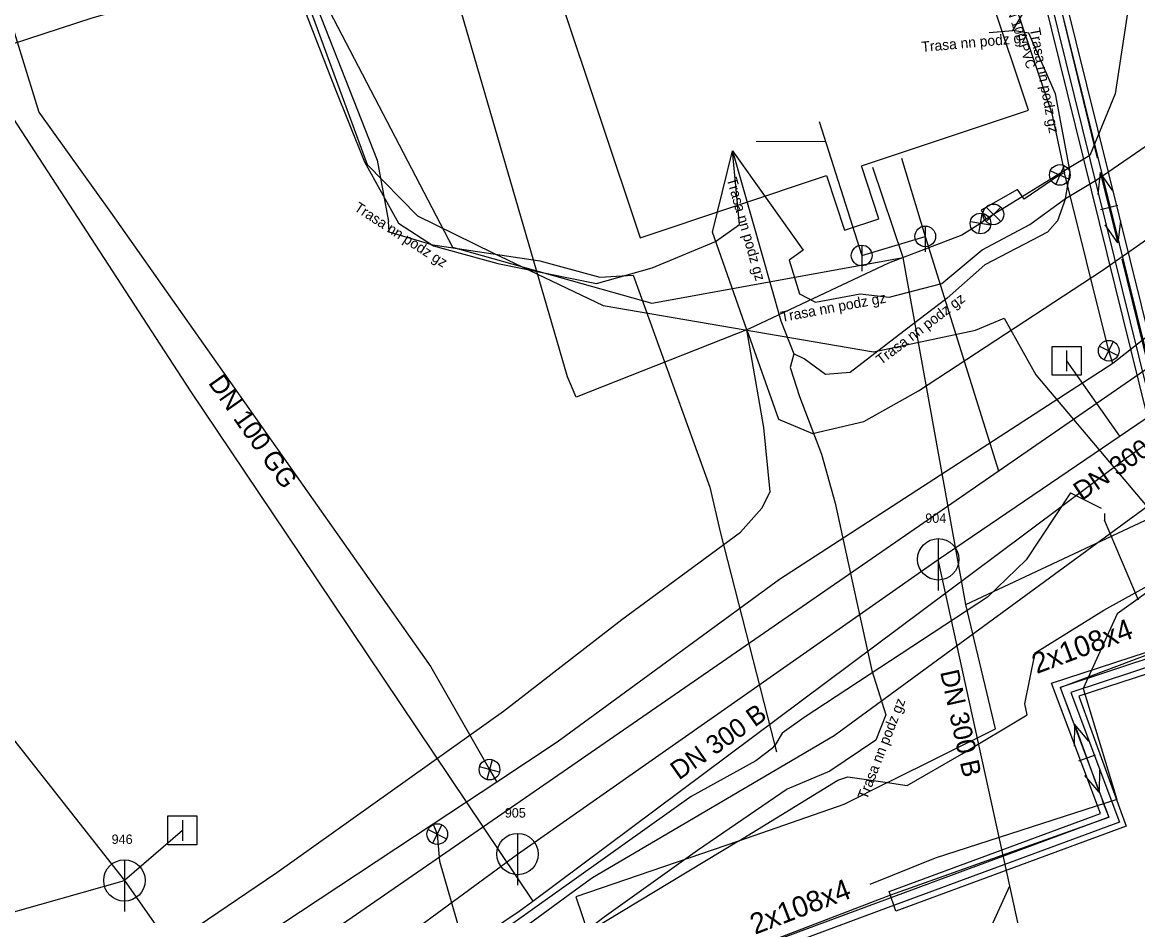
# Model space of a CAD drawing. Extents: x -492431 to -49223, y -1127123 to -112687.
# Drawn here: x -492298.3 to -492244.4, y -1127017.5 to -1126974.3 of the extents above; entities that cross this region are included whole.
import ezdxf

# ---------------------------------------------------------------- set-up
doc = ezdxf.new("R2010")
doc.units = 0
for name, color, linetype in [('Vrstva 1', 7, 'Continuous'), ('Vrstva 11', 7, 'Continuous'), ('Vrstva 15', 7, 'Continuous'), ('Vrstva 17', 7, 'Continuous'), ('Vrstva 19', 7, 'Continuous'), ('Vrstva 20', 7, 'Continuous'), ('Vrstva 22', 7, 'Continuous'), ('Vrstva 24', 7, 'Continuous'), ('Vrstva 26', 7, 'Continuous'), ('Vrstva 35', 7, 'Continuous'), ('Vrstva 44', 7, 'Continuous'), ('Vrstva 45', 7, 'Continuous'), ('Vrstva 49', 7, 'Continuous'), ('Vrstva 5', 7, 'Continuous'), ('Vrstva 6', 7, 'Continuous'), ('Vrstva 9', 7, 'Continuous')]:
    doc.layers.add(name, color=color, linetype=linetype)

msp = doc.modelspace()

# ---------------------------------------------------------------- linework, layer by layer
at = {"layer": 'Vrstva 1'}
for points in [[(-492325.249, -1126898.739), (-492322.642, -1126907.396), (-492319.91, -1126916.162), (-492316.366, -1126927.531), (-492313.526, -1126937.493), (-492311.824, -1126943.46), (-492307.449, -1126957.644), (-492305.431, -1126964.56), (-492304.672, -1126966.837), (-492303.375, -1126970.726), (-492302.901, -1126972.466), (-492290.152, -1126992.096), (-492284.841, -1127000), (-492275.169, -1127014.395), (-492273.59, -1127016.746)], [(-492311.084, -1127042.338), (-492308.422, -1127040.519), (-492280.878, -1127021.698), (-492274.246, -1127017.236), (-492273.59, -1127016.746), (-492251.166, -1127000), (-492244.915, -1126995.332), (-492241.648, -1126993.025), (-492237.012, -1126989.75)]]:
    msp.add_lwpolyline(points, dxfattribs=at)
at = {"layer": 'Vrstva 11'}
for points in [[(-492295.29, -1126949.58), (-492293.18, -1126956.81), (-492288.33, -1126969.66), (-492285.99, -1126968.78), (-492277.47, -1126985.14), (-492267.85, -1126987.85), (-492255.7, -1126985.65)], [(-492212.36, -1126974.41), (-492232.81, -1126989.56), (-492259.04, -1127008.76), (-492270.71, -1127015.63)], [(-492255.7, -1126985.65), (-492257.16, -1126981.29)], [(-492252.68, -1127002.42), (-492255.7, -1126985.65)], [(-492252.68, -1127002.42), (-492240.08, -1126996.5), (-492239.44, -1126998.4)], [(-492256.45, -1127011.02), (-492255.5, -1127011.16), (-492252.88, -1127009.65), (-492249.71, -1127007.75), (-492249.83, -1127007.22), (-492249.33, -1127004.75), (-492246, -1127002.69), (-492242.83, -1127000.94), (-492239.33, -1126998.73)], [(-492256.45, -1127011.02), (-492251.24, -1127008.42), (-492252.68, -1127002.42)], [(-492263.66, -1127013.85), (-492258.85, -1127010.91), (-492258.38, -1127010.75), (-492256.45, -1127011.02)], [(-492256.45, -1127011.02), (-492258.57, -1127012.08), (-492263.66, -1127013.85)], [(-492263.66, -1127013.85), (-492271.51, -1127016.54), (-492270.94, -1127018.25)], [(-492263.66, -1127013.85), (-492270.94, -1127018.25)], [(-492270.71, -1127015.63), (-492271.65, -1127016.3), (-492296.86, -1127034.79), (-492304.07, -1127039.47)]]:
    msp.add_lwpolyline(points, dxfattribs=at)
at = {"layer": 'Vrstva 15'}
for p, q in [((-492259.759, -1126979.073), (-492257.706, -1126985.55)), ((-492262.811, -1126980.031), (-492259.454, -1126980.036)), ((-492255.781, -1126980.848), (-492254.634, -1126984.625)), ((-492319.259, -1126982.82), (-492293.327, -1127015.749)), ((-492257.706, -1126985.55), (-492254.634, -1126984.625)), ((-492254.634, -1126984.625), (-492251.095, -1126995.958)), ((-492254.006, -1127000.233), (-492235.336, -1126987.536)), ((-492247.807, -1126990.639), (-492245.254, -1126994.28)), ((-492274.331, -1127014.474), (-492254.006, -1127000.233)), ((-492250.545, -1127016.013), (-492254.006, -1127000.233)), ((-492290.527, -1127013.33), (-492293.327, -1127015.749)), ((-492287.427, -1127024.093), (-492274.331, -1127014.474)), ((-492307.936, -1127019.882), (-492293.327, -1127015.749)), ((-492293.327, -1127015.749), (-492287.427, -1127024.093)), ((-492252.489, -1127020.253), (-492250.544, -1127016.013)), ((-492247.397, -1127030.362), (-492250.545, -1127016.013))]:
    msp.add_line(p, q, dxfattribs=at)
msp.add_lwpolyline([(-492348.18, -1127063.194), (-492288.462, -1127021.762), (-492226.623, -1126979.059)], dxfattribs=at)
at = {"layer": 'Vrstva 17'}
for p, q in [((-492254.634, -1126984.125), (-492254.634, -1126985.375)), ((-492257.706, -1126985.05), (-492257.706, -1126986.3)), ((-492247.807, -1126990.139), (-492247.807, -1126991.139)), ((-492254.006, -1126999.233), (-492254.006, -1127001.733)), ((-492290.527, -1127012.83), (-492290.527, -1127013.83)), ((-492274.331, -1127013.474), (-492274.331, -1127015.974)), ((-492293.327, -1127014.749), (-492293.327, -1127017.249))]:
    msp.add_line(p, q, dxfattribs=at)
for points in [[(-492248.507, -1126989.939), (-492247.108, -1126989.939), (-492247.108, -1126991.339), (-492248.507, -1126991.339), (-492248.507, -1126989.939)], [(-492291.227, -1127012.631), (-492289.828, -1127012.631), (-492289.828, -1127014.03), (-492291.227, -1127014.03), (-492291.227, -1127012.631)]]:
    msp.add_lwpolyline(points, dxfattribs=at)
for centre, radius in [((-492254.634, -1126984.625), 0.5), ((-492257.706, -1126985.55), 0.5), ((-492254.006, -1127000.233), 1), ((-492274.331, -1127014.474), 1), ((-492293.327, -1127015.749), 1)]:
    msp.add_circle(centre, radius, dxfattribs=at)
at = {"layer": 'Vrstva 20'}
for p, q in [((-492302.176, -1126963.33), (-492297.462, -1126978.624)), ((-492297.462, -1126978.624), (-492294.001, -1126983.458)), ((-492247.905, -1126981.562), (-492248.131, -1126981.658)), ((-492245.77, -1126990.15), (-492247.905, -1126981.562)), ((-492294.001, -1126983.458), (-492278.528, -1127005.422)), ((-492251.683, -1126983.801), (-492251.966, -1126984.002)), ((-492245.569, -1126990.776), (-492245.77, -1126990.15)), ((-492278.528, -1127005.422), (-492275.687, -1127010.392)), ((-492275.687, -1127010.392), (-492275.341, -1127011)), ((-492275.341, -1127011), (-492278.406, -1127013.025)), ((-492278.406, -1127013.025), (-492278.21, -1127013.51))]:
    msp.add_line(p, q, dxfattribs=at)
for points in [[(-492258.655, -1126937.855), (-492256.335, -1126940.299), (-492254.087, -1126946.247), (-492250.053, -1126957.353), (-492247.459, -1126963.781), (-492245.575, -1126969.401), (-492244.821, -1126973.507), (-492245.464, -1126977.737), (-492246.677, -1126980.722), (-492247.678, -1126981.308), (-492251.339, -1126983.561)], [(-492251.966, -1126984.002), (-492252.867, -1126984.562), (-492256.417, -1126985.913), (-492263.134, -1126989.093), (-492271.494, -1126992.401), (-492271.919, -1126991.405), (-492277.913, -1126970.81), (-492278.388, -1126969.283), (-492287.981, -1126972.121), (-492294.895, -1126974.083), (-492300.39, -1126975.871), (-492310.81, -1126979.945), (-492316.118, -1126984.31), (-492323.327, -1126989.676), (-492325.365, -1126991.119)], [(-492252.187, -1126972.839), (-492250.649, -1126972.391), (-492248.52, -1126978.691), (-492248.003, -1126981.105), (-492247.905, -1126981.562)], [(-492248.131, -1126981.658), (-492249.857, -1126982.82), (-492250.172, -1126982.359), (-492251.938, -1126983.356), (-492251.683, -1126983.801)], [(-492251.339, -1126983.561), (-492251.393, -1126983.594), (-492251.683, -1126983.801)], [(-492225.92, -1127031.19), (-492226.098, -1127030.529), (-492230.807, -1127017.938), (-492238.16, -1126995.84), (-492239.164, -1126992.202), (-492241.237, -1126987.362), (-492245.569, -1126990.776)], [(-492245.569, -1126990.776), (-492261.681, -1127001.199), (-492272.42, -1127009.071), (-492275.341, -1127011)], [(-492278.406, -1127013.025), (-492299.412, -1127026.894), (-492316.583, -1127039.151), (-492312.88, -1127049.25), (-492307.84, -1127067.71), (-492302.01, -1127083.53), (-492298.428, -1127092.757)], [(-492278.21, -1127013.51), (-492278.11, -1127014.81), (-492277.09, -1127018.33), (-492276.55, -1127020.13), (-492263.48, -1127057.09), (-492263.27, -1127057.7)]]:
    msp.add_lwpolyline(points, dxfattribs=at)
at = {"layer": 'Vrstva 22'}
for p, q in [((-492247.929, -1126981.206), (-492248.333, -1126982.11)), ((-492248.583, -1126981.456), (-492247.679, -1126981.86)), ((-492252.048, -1126984.49), (-492251.884, -1126983.514)), ((-492251.689, -1126983.911), (-492250.989, -1126983.211)), ((-492250.989, -1126983.911), (-492251.689, -1126983.211)), ((-492251.478, -1126984.084), (-492252.454, -1126983.92)), ((-492246.211, -1126989.924), (-492245.329, -1126990.376)), ((-492245.996, -1126990.591), (-492245.544, -1126989.709)), ((-492275.557, -1127009.914), (-492275.817, -1127010.87)), ((-492275.209, -1127010.522), (-492276.165, -1127010.262)), ((-492278.432, -1127013.952), (-492277.988, -1127013.068)), ((-492278.652, -1127013.288), (-492277.768, -1127013.732))]:
    msp.add_line(p, q, dxfattribs=at)
for centre, radius in [((-492248.131, -1126981.658), 0.5), ((-492248.131, -1126981.658), 0.025), ((-492251.339, -1126983.561), 0.5), ((-492251.966, -1126984.002), 0.5), ((-492251.339, -1126983.561), 0.025), ((-492251.966, -1126984.002), 0.025), ((-492245.77, -1126990.15), 0.5), ((-492245.77, -1126990.15), 0.025), ((-492275.687, -1127010.392), 0.5), ((-492275.687, -1127010.392), 0.025), ((-492278.21, -1127013.51), 0.5), ((-492278.21, -1127013.51), 0.025)]:
    msp.add_circle(centre, radius, dxfattribs=at)
at = {"layer": 'Vrstva 26'}
for p, q in [((-492284.85, -1126971.41), (-492281.12, -1126980.95)), ((-492281.12, -1126980.95), (-492280.56, -1126983.9)), ((-492280.54, -1126984.43), (-492280.56, -1126983.9)), ((-492278.52, -1126985.02), (-492280.54, -1126984.43)), ((-492278.52, -1126985.02), (-492273.26, -1126985.81)), ((-492273.26, -1126985.81), (-492270.35, -1126986.59)), ((-492270.35, -1126986.59), (-492268.74, -1126986.5)), ((-492268.74, -1126986.5), (-492265.05, -1126996.75)), ((-492265.05, -1126996.75), (-492264.54, -1126998.91)), ((-492247.62, -1126997.02), (-492249.76, -1127000.26)), ((-492247.62, -1126997.02), (-492246.14, -1126997.76)), ((-492245.97, -1126998.01), (-492245.97, -1126998.34)), ((-492244.33, -1127002.2), (-492245.97, -1126998.34)), ((-492264.54, -1126998.91), (-492261.9, -1127009.22)), ((-492249.76, -1127000.26), (-492251.62, -1127002.06)), ((-492251.62, -1127002.06), (-492260.49, -1127007.88)), ((-492260.49, -1127007.88), (-492261.55, -1127008.63)), ((-492261.55, -1127008.63), (-492261.9, -1127009.22)), ((-492262.01, -1127009.35), (-492262.82, -1127009.97)), ((-492262.01, -1127009.35), (-492261.9, -1127009.22)), ((-492261.9, -1127009.22), (-492261.82, -1127009.54)), ((-492262.82, -1127009.97), (-492265.94, -1127011.7)), ((-492265.94, -1127011.7), (-492274.67, -1127017.91))]:
    msp.add_line(p, q, dxfattribs=at)
at = {"layer": 'Vrstva 35'}
for points in [[(-492294.32, -1126954.25), (-492289.61, -1126968.74), (-492285.36, -1126971.01), (-492284.64, -1126972.86), (-492281.6, -1126981.15), (-492279.17, -1126983.63), (-492275.52, -1126985.42), (-492270.19, -1126987.97), (-492257.13, -1126990.21), (-492252.21, -1126989.15), (-492250.82, -1126988.57), (-492249.29, -1126991.31), (-492241.74, -1127000.27)], [(-492241.74, -1127000.27), (-492245.36, -1127002.86), (-492247.01, -1127006.47), (-492245.37, -1127011.84), (-492254.16, -1127014.67), (-492257.31, -1127015.95)]]:
    msp.add_lwpolyline(points, dxfattribs=at)
at = {"layer": 'Vrstva 44'}
for p, q in [((-492248.69, -1126969.86), (-492240.68, -1127002.2)), ((-492241.65, -1127002.44), (-492249.37, -1126971.21)), ((-492248.54, -1127006.21), (-492241.95, -1127004.07)), ((-492241.7, -1127005.04), (-492247.21, -1127006.85)), ((-492246.16, -1127012.52), (-492248.54, -1127006.21)), ((-492247.21, -1127006.85), (-492244.92, -1127013.13)), ((-492256.37, -1127016.29), (-492246.16, -1127012.52)), ((-492244.92, -1127013.13), (-492256.06, -1127017.24)), ((-492256.06, -1127017.24), (-492256.37, -1127016.29))]:
    msp.add_line(p, q, dxfattribs=at)
at = {"layer": 'Vrstva 45'}
for p, q in [((-492240.57, -1127003.92), (-492248.9, -1126970.26)), ((-492248.88, -1126970.33), (-492246.32, -1126980.84)), ((-492240.97, -1127003.97), (-492249.15, -1126970.82)), ((-492246.178, -1126981.545), (-492245.33, -1126984.94)), ((-492245.336, -1126983.138), (-492246.171, -1126983.347)), ((-492245.58, -1126984.17), (-492245.58, -1126984.17)), ((-492245.13, -1126985.72), (-492240.37, -1127005.23)), ((-492248.12, -1127006.42), (-492238.35, -1127002.76)), ((-492240.95, -1127004.05), (-492248.12, -1127006.42)), ((-492240.69, -1127004.39), (-492247.6, -1127006.67)), ((-492248.12, -1127006.42), (-492247.64, -1127007.69)), ((-492248.12, -1127006.42), (-492245.77, -1127012.69)), ((-492247.6, -1127006.67), (-492245.25, -1127012.93)), ((-492247.419, -1127008.198), (-492246.23, -1127011.49)), ((-492246.42, -1127009.698), (-492247.229, -1127009.99)), ((-492246.08, -1127011.88), (-492245.77, -1127012.69)), ((-492246.04, -1127011.97), (-492246.04, -1127011.97)), ((-492245.77, -1127012.69), (-492256.47, -1127016.65)), ((-492256.3, -1127016.44), (-492245.77, -1127012.69)), ((-492245.25, -1127012.93), (-492256.42, -1127017.05)), ((-492246.55, -1127012.97), (-492246.55, -1127012.97)), ((-492268.47, -1127021.1), (-492256.3, -1127016.44)), ((-492256.47, -1127016.65), (-492267.16, -1127020.6)), ((-492256.42, -1127017.05), (-492266.76, -1127020.88))]:
    msp.add_line(p, q, dxfattribs=at)
for points in [[(-492245.571, -1126982.424), (-492246.178, -1126981.545), (-492246.299, -1126982.606)], [(-492245.208, -1126983.879), (-492245.33, -1126984.94), (-492245.936, -1126984.061)], [(-492246.727, -1127009.012), (-492247.419, -1127008.198), (-492247.432, -1127009.266)], [(-492246.217, -1127010.422), (-492246.23, -1127011.49), (-492246.922, -1127010.677)]]:
    msp.add_lwpolyline(points, dxfattribs=at)
at = {"layer": 'Vrstva 49'}
for p, q in [((-492275.01, -1126964.93), (-492268.41, -1126984.69)), ((-492249.64, -1126978.52), (-492252.31, -1126970.54)), ((-492257.72, -1126981.22), (-492249.64, -1126978.52)), ((-492256.87, -1126983.77), (-492257.72, -1126981.22)), ((-492268.41, -1126984.69), (-492259.41, -1126981.69)), ((-492259.41, -1126981.69), (-492258.53, -1126984.32)), ((-492258.53, -1126984.32), (-492256.87, -1126983.77))]:
    msp.add_line(p, q, dxfattribs=at)
at = {"layer": 'Vrstva 5'}
for points in [[(-492250.41, -1126974.67), (-492249.94, -1126973.88), (-492249.73, -1126972.55), (-492249.78, -1126970.37), (-492250.43, -1126965.95), (-492252.15, -1126959.68), (-492254.16, -1126953.46), (-492256.48, -1126947.52), (-492259.2, -1126941.97), (-492262.25, -1126936.53), (-492264.141, -1126933.048), (-492266.18, -1126929.478)], [(-492285.47, -1126967.36), (-492285.35, -1126968.15), (-492285.5, -1126971.42), (-492283.18, -1126977.41), (-492281.72, -1126981.02), (-492280.08, -1126983.99), (-492278.39, -1126985.08), (-492275.28, -1126985.93), (-492270.52, -1126986.91), (-492267.83, -1126986.14), (-492264.77, -1126984.88), (-492263.61, -1126984.05), (-492263.944, -1126980.495)], [(-492251.54, -1126974.772), (-492250.41, -1126974.67)], [(-492247.86, -1126982.8), (-492247.64, -1126981.5), (-492248.34, -1126977.74), (-492249.63, -1126974.81), (-492250.41, -1126974.67)], [(-492247.86, -1126982.8), (-492246.33, -1126981.88), (-492243.45, -1126979.9), (-492242.32, -1126979.08), (-492240.98, -1126978.54), (-492240.14, -1126979.24), (-492239.73, -1126979.99), (-492239.54, -1126981.13), (-492238.98, -1126982.44), (-492235.85, -1126989.99), (-492234.78, -1126992.16), (-492233.33, -1126996.13), (-492231.37, -1127001.93), (-492230.56, -1127005.29), (-492229.92, -1127005.56)], [(-492263.944, -1126980.495), (-492261.61, -1126988.7), (-492260.99, -1126990.3)], [(-492263.944, -1126980.495), (-492260.532, -1126985.291), (-492261.203, -1126985.779), (-492260.715, -1126987.406), (-492259.93, -1126987.8), (-492257.78, -1126987.4), (-492256.38, -1126987.56), (-492253.83, -1126986.9), (-492251.888, -1126985.269), (-492249.58, -1126984.05), (-492247.86, -1126982.8)], [(-492247.86, -1126982.8), (-492248.25, -1126983.87), (-492248.72, -1126984.42), (-492251.76, -1126986), (-492253.58, -1126987.61), (-492255.88, -1126989.36), (-492258.26, -1126991.21), (-492259.45, -1126991.3), (-492260.49, -1126990.55), (-492260.99, -1126990.3)], [(-492260.99, -1126990.3), (-492261.16, -1126990.96), (-492260.71, -1126992.36), (-492259.65, -1126995.15), (-492258.98, -1126997.51), (-492257.97, -1127002.17), (-492257.21, -1127005.6), (-492256.54, -1127007.74), (-492257.02, -1127008.97), (-492259.24, -1127010.47), (-492261.3, -1127011.34), (-492265.64, -1127014.31), (-492270.14, -1127017.52), (-492271.47, -1127018.54)]]:
    msp.add_lwpolyline(points, dxfattribs=at)
at = {"layer": 'Vrstva 6'}
for points in [[(-492263.25, -1126989.144), (-492261.731, -1126993.462), (-492260.081, -1126994.156), (-492257.598, -1126993.574), (-492254.965, -1126992.082), (-492246.089, -1126986.277), (-492240.252, -1126982.203), (-492231.099, -1126976.147), (-492223.494, -1126971.254), (-492218.08, -1126966.947), (-492211.53, -1126962.253), (-492210.012, -1126960.949), (-492209.47, -1126959.677), (-492209.378, -1126957.504), (-492207.928, -1126954.459), (-492206.61, -1126951.636), (-492205.409, -1126950.046), (-492203.864, -1126949.243), (-492197.049, -1126946.798), (-492187.754, -1126943.138), (-492184.528, -1126941.897), (-492182.28, -1126941.631), (-492177.997, -1126941.584), (-492174.72, -1126942.286)], [(-492377.404, -1127078.692), (-492367.081, -1127071.634), (-492360.42, -1127066.894), (-492347.798, -1127058.645), (-492342.231, -1127054.327), (-492337.859, -1127051.471), (-492330.214, -1127045.977), (-492316.973, -1127036.991), (-492306.678, -1127029.596), (-492296.462, -1127022.487), (-492285.965, -1127015.358), (-492275.009, -1127007.561), (-492269.292, -1127003.141), (-492263.556, -1126998.914), (-492262.523, -1126997.76), (-492262.128, -1126996.973), (-492262.434, -1126993.868), (-492263.25, -1126989.144), (-492264.906, -1126984.417), (-492263.944, -1126980.495)]]:
    msp.add_lwpolyline(points, dxfattribs=at)

# ---------------------------------------------------------------- texts
at = {"layer": 'Vrstva 19'}
for rotation, p in [(34.2186, (-492247.079, -1126997.423)), (282.3707, (-492253.921, -1127005.669)), (35.0176, (-492266.538, -1127010.925))]:
    msp.add_text('DN 300 B', height=0.9099, rotation=rotation, dxfattribs=at).set_placement(p)
for s, p in [('904', (-492254.634, -1126998.469)), ('905', (-492274.948, -1127012.71)), ('946', (-492293.944, -1127013.985))]:
    msp.add_text(s, height=0.4549, dxfattribs=at).set_placement(p)
at = {"layer": 'Vrstva 24'}
for s, height, rotation, p in [('DN 100 PVC', 0.455, 288.672, (-492250.831, -1126973.274)), ('DN 100 GG', 0.9099, 305.1636, (-492289.304, -1126991.706))]:
    msp.add_text(s, height=height, rotation=rotation, dxfattribs=at).set_placement(p)
at = {"layer": 'Vrstva 49'}
for rotation, p in [(20.5207, (-492249.248, -1127005.777)), (20.9377, (-492262.861, -1127018.378))]:
    msp.add_text('2x108x4', height=1, rotation=rotation, dxfattribs=at).set_placement(p)
at = {"layer": 'Vrstva 9'}
for rotation, p in [(5.1579, (-492254.794, -1126975.718)), (280.546, (-492249.586, -1126974.596)), (285.8785, (-492264.233, -1126981.855)), (327.1792, (-492282.269, -1126983.352)), (10.5392, (-492261.569, -1126988.766)), (37.2664, (-492256.771, -1126990.855)), (68.6821, (-492257.457, -1127011.876))]:
    msp.add_text('Trasa nn podz gz', height=0.5, rotation=rotation, dxfattribs=at).set_placement(p)

doc.saveas('drawing.dxf')
